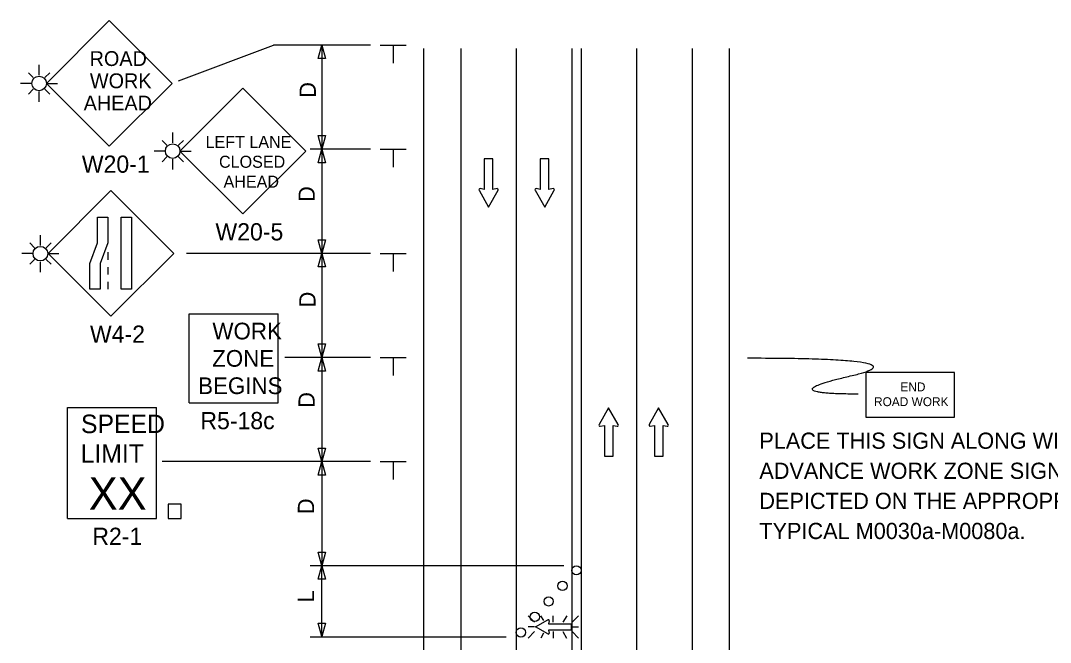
# Model space of a CAD drawing. Extents: x 16731 to 18475, y 7218 to 8213.
# Drawn here: x 16731.1 to 17176, y 7944.5 to 8213.2 of the extents above; entities that cross this region are included whole.
import ezdxf

# ---------------------------------------------------------------- set-up
doc = ezdxf.new("R2010")
doc.units = 0
for name, color, linetype in [('ALI_LEGAL_EX', 7, 'Continuous'), ('MT_SCRATCH_LEVEL_E', 7, 'Continuous'), ('PAVT_EDGE_EX', 7, 'Continuous'), ('TRAFFIC_SIGNS_PR', 7, 'Continuous'), ('TYPICAL_TEXT_DIMEN_PR', 7, 'Continuous')]:
    doc.layers.add(name, color=color, linetype=linetype)

msp = doc.modelspace()

# ---------------------------------------------------------------- linework, layer by layer
at = {"layer": 'ALI_LEGAL_EX'}
for p, q in [((16945.19, 8201.12), (16945.19, 7350.01)), ((16997.19, 8201.12), (16997.19, 7350.01))]:
    msp.add_line(p, q, dxfattribs=at)
for points in [[(16945.19, 8201.12), (16945.19, 8176.12)], [(16997.19, 8201.12), (16997.19, 8176.12)], [(16945.19, 8101.12), (16945.19, 8076.12)], [(16997.19, 8101.12), (16997.19, 8076.12)], [(16945.19, 8001.12), (16945.19, 7976.12)], [(16997.19, 8001.12), (16997.19, 7976.12)]]:
    msp.add_lwpolyline(points, dxfattribs=at)
at = {"layer": 'MT_SCRATCH_LEVEL_E'}
for p, q in [((16935.11, 8153.5), (16931.37, 8153.5)), ((16931.37, 8153.5), (16931.37, 8140.24)), ((16935.11, 8153.5), (16931.37, 8153.5)), ((16931.37, 8153.5), (16931.37, 8140.24)), ((16935.11, 8140.24), (16935.11, 8153.5)), ((16935.11, 8140.24), (16935.11, 8153.5)), ((16959.34, 8153.5), (16955.6, 8153.5)), ((16955.6, 8153.5), (16955.6, 8140.24)), ((16959.34, 8153.5), (16955.6, 8153.5)), ((16955.6, 8153.5), (16955.6, 8140.24)), ((16959.34, 8140.24), (16959.34, 8153.5)), ((16959.34, 8140.24), (16959.34, 8153.5)), ((16929.11, 8139.87), (16933.26, 8132.63)), ((16929.11, 8139.87), (16933.26, 8132.63)), ((16931.37, 8140.24), (16929.59, 8140.56)), ((16931.37, 8140.24), (16929.59, 8140.56)), ((16933.26, 8132.63), (16937.37, 8139.87)), ((16933.26, 8132.63), (16937.37, 8139.87)), ((16936.89, 8140.56), (16935.11, 8140.24)), ((16936.89, 8140.56), (16935.11, 8140.24)), ((16953.35, 8139.87), (16957.49, 8132.63)), ((16953.35, 8139.87), (16957.49, 8132.63)), ((16955.6, 8140.24), (16953.83, 8140.56)), ((16955.6, 8140.24), (16953.83, 8140.56)), ((16957.49, 8132.63), (16961.6, 8139.87)), ((16957.49, 8132.63), (16961.6, 8139.87)), ((16961.12, 8140.56), (16959.34, 8140.24)), ((16961.12, 8140.56), (16959.34, 8140.24)), ((16985.12, 8045.83), (16981.01, 8038.59)), ((16985.12, 8045.83), (16981.01, 8038.59)), ((16989.26, 8038.59), (16985.12, 8045.83)), ((16989.26, 8038.59), (16985.12, 8045.83)), ((17006.72, 8045.83), (17002.61, 8038.59)), ((17006.72, 8045.83), (17002.61, 8038.59)), ((17010.87, 8038.59), (17006.72, 8045.83)), ((17010.87, 8038.59), (17006.72, 8045.83)), ((16981.49, 8037.91), (16983.26, 8038.22)), ((16981.49, 8037.91), (16983.26, 8038.22)), ((16983.26, 8038.22), (16983.26, 8024.97)), ((16983.26, 8038.22), (16983.26, 8024.97)), ((16987.01, 8024.97), (16987.01, 8038.22)), ((16987.01, 8038.22), (16988.78, 8037.91)), ((16987.01, 8024.97), (16987.01, 8038.22)), ((16987.01, 8038.22), (16988.78, 8037.91)), ((17003.09, 8037.91), (17004.87, 8038.22)), ((17003.09, 8037.91), (17004.87, 8038.22)), ((17004.87, 8038.22), (17004.87, 8024.97)), ((17004.87, 8038.22), (17004.87, 8024.97)), ((17008.61, 8024.97), (17008.61, 8038.22)), ((17008.61, 8038.22), (17010.39, 8037.91)), ((17008.61, 8024.97), (17008.61, 8038.22)), ((17008.61, 8038.22), (17010.39, 8037.91)), ((16983.26, 8024.97), (16987.01, 8024.97)), ((16983.26, 8024.97), (16987.01, 8024.97)), ((17004.87, 8024.97), (17008.61, 8024.97)), ((17004.87, 8024.97), (17008.61, 8024.97))]:
    msp.add_line(p, q, dxfattribs=at)
for centre, start, end in [((16929.52, 8140.09), 80.0362, 209.7731), ((16929.52, 8140.09), 80.0362, 209.7731), ((16936.96, 8140.1), 330.4248, 99.9638), ((16936.96, 8140.1), 330.4248, 99.9638), ((16953.76, 8140.09), 80.0362, 209.7731), ((16953.76, 8140.09), 80.0362, 209.7731), ((16961.2, 8140.1), 330.4248, 99.9638), ((16961.2, 8140.1), 330.4248, 99.9638), ((16981.41, 8038.37), 150.4248, 279.9638), ((16981.41, 8038.37), 150.4248, 279.9638), ((16988.85, 8038.37), 260.0362, 29.7731), ((16988.85, 8038.37), 260.0362, 29.7731), ((17003.02, 8038.37), 150.4248, 279.9638), ((17003.02, 8038.37), 150.4248, 279.9638), ((17010.46, 8038.37), 260.0362, 29.7731), ((17010.46, 8038.37), 260.0362, 29.7731)]:
    msp.add_arc(centre, 0.463, start, end, dxfattribs=at)
at = {"layer": 'PAVT_EDGE_EX'}
for p, q in [((16905.19, 8201.12), (16905.19, 7350.01)), ((16921.19, 8201.12), (16921.19, 7350.01)), ((16969.19, 8201.12), (16969.19, 7912.67)), ((16973.19, 8201.12), (16973.19, 7913.05)), ((17021.19, 8201.12), (17021.19, 7350.01)), ((17037.19, 8201.12), (17037.19, 7350.01))]:
    msp.add_line(p, q, dxfattribs=at)
at = {"layer": 'TRAFFIC_SIGNS_PR'}
for p, q in [((16769.35, 8213.18), (16742.19, 8186.03)), ((16796.5, 8186.03), (16769.35, 8213.18)), ((16739.04, 8189.58), (16739.04, 8194.08)), ((16736.53, 8188.54), (16734.43, 8190.65)), ((16741.55, 8188.54), (16743.66, 8190.65)), ((16735.89, 8186.03), (16731.06, 8186.03)), ((16736.53, 8183.52), (16734.43, 8181.42)), ((16739.04, 8178.07), (16739.04, 8182.48)), ((16741.55, 8183.52), (16743.66, 8181.42)), ((16742.19, 8186.03), (16769.35, 8158.88)), ((16742.19, 8186.03), (16747.07, 8186.03)), ((16769.35, 8158.88), (16796.5, 8186.03)), ((16827.08, 8183.94), (16799.92, 8156.79)), ((16854.23, 8156.79), (16827.08, 8183.94)), ((16796.77, 8160.34), (16796.77, 8164.83)), ((16794.26, 8159.3), (16792.16, 8161.4)), ((16799.28, 8159.3), (16801.39, 8161.4)), ((16793.62, 8156.79), (16788.79, 8156.79)), ((16799.92, 8156.79), (16804.8, 8156.79)), ((16799.92, 8156.79), (16827.08, 8129.64)), ((16827.08, 8129.64), (16854.23, 8156.79)), ((16794.26, 8154.28), (16792.16, 8152.17)), ((16796.77, 8148.83), (16796.77, 8153.24)), ((16799.28, 8154.28), (16801.39, 8152.17)), ((16770.07, 8139.73), (16742.92, 8112.58)), ((16797.22, 8112.58), (16770.07, 8139.73)), ((16739.61, 8116.03), (16739.61, 8120.53)), ((16737.1, 8114.99), (16735, 8117.1)), ((16742.12, 8114.99), (16744.23, 8117.1)), ((16736.46, 8112.48), (16731.63, 8112.48)), ((16742.76, 8112.48), (16747.64, 8112.48)), ((16742.92, 8112.58), (16770.07, 8085.42)), ((16768.82, 8113.07), (16768.82, 8109.87)), ((16770.07, 8085.42), (16797.22, 8112.58)), ((16737.1, 8109.97), (16735, 8107.87)), ((16739.61, 8104.52), (16739.61, 8108.93)), ((16742.12, 8109.97), (16744.23, 8107.87)), ((16768.82, 8106.67), (16768.82, 8103.47)), ((16768.82, 8100.27), (16768.82, 8097.07)), ((16803.94, 8048.05), (16803.94, 8086.45)), ((16803.94, 8086.45), (16842.34, 8086.45)), ((16842.34, 8048.05), (16842.34, 8086.45)), ((16751.38, 8046.06), (16789.78, 8046.06)), ((16751.38, 7998.06), (16751.38, 8046.06)), ((16789.78, 7998.06), (16789.78, 8046.06)), ((16803.94, 8048.05), (16842.34, 8048.05)), ((16751.38, 7998.06), (16789.78, 7998.06)), ((16950.31, 7956.02), (16953.13, 7953.2)), ((16955.74, 7956.02), (16956.95, 7953.93)), ((16961.21, 7953.2), (16961.21, 7956.02)), ((16967, 7956.02), (16965.37, 7953.2)), ((16969.3, 7953.2), (16972.12, 7956.02)), ((16953.13, 7951.17), (16950.31, 7951.17)), ((16969.3, 7951.17), (16972.12, 7951.17)), ((16950.31, 7946.32), (16953.13, 7949.14)), ((16957.03, 7948.5), (16955.77, 7946.32)), ((16961.21, 7949.14), (16961.21, 7946.32)), ((16965.35, 7949.14), (16966.97, 7946.32)), ((16969.3, 7949.14), (16972.12, 7946.31))]:
    msp.add_line(p, q, dxfattribs=at)
for points in [[(16768.82, 8128.31), (16768.82, 8117.13), (16765.48, 8108.25), (16765.48, 8097.07), (16760.98, 8097.07), (16760.98, 8108.25), (16764.33, 8117.13), (16764.33, 8128.31)], [(16778.96, 8128.31), (16778.96, 8097.07), (16774.46, 8097.07), (16774.46, 8128.31)], [(17096.17, 8041.85), (17134.57, 8041.85), (17134.57, 8061.05), (17096.17, 8061.05)], [(16794.8, 7998.06), (16800.39, 7998.06), (16800.39, 8004.23), (16794.8, 8004.23)]]:
    msp.add_lwpolyline(points, close=True, dxfattribs=at)
for points in [[(16958.89, 7948.15), (16953.58, 7951.17), (16958.89, 7954.21)], [(16959.39, 7953.85), (16959.16, 7952.55), (16968.88, 7952.55), (16968.88, 7949.81), (16959.16, 7949.81), (16959.39, 7948.51)]]:
    msp.add_lwpolyline(points, dxfattribs=at)
for centre, radius in [((16739.04, 8186.03), 3.15), ((16796.77, 8156.79), 3.15), ((16739.61, 8112.48), 3.15), ((16971.19, 7975.63), 2), ((16965.19, 7968.92), 2), ((16959.19, 7962.21), 2), ((16953.19, 7955.5), 2), ((16947.2, 7948.79), 2)]:
    msp.add_circle(centre, radius, dxfattribs=at)
for centre, start, end in [((16959.05, 7953.91), 350.0407, 118.5167), ((16959.05, 7948.45), 241.1084, 9.2692)]:
    msp.add_arc(centre, 0.341, start, end, dxfattribs=at)
msp.add_open_spline([(17092.98, 8051.79), (17055.19, 8051.79), (17123.21, 8067.27), (17045.07, 8067.27)], degree=2, dxfattribs=at)
at = {"layer": 'TYPICAL_TEXT_DIMEN_PR'}
for p, q in [((16799.32, 8187.1), (16840.31, 8202.61)), ((16882.19, 8202.61), (16840.31, 8202.61)), ((16859.62, 8196.75), (16861.19, 8202.61)), ((16861.19, 8202.61), (16861.19, 8157.61)), ((16861.19, 8202.61), (16862.76, 8196.75)), ((16886.44, 8202.61), (16897.69, 8202.61)), ((16892.07, 8202.61), (16892.07, 8194.83)), ((16861.19, 8196.75), (16859.62, 8196.75)), ((16862.76, 8196.75), (16861.19, 8196.75)), ((16861.19, 8157.61), (16859.62, 8163.48)), ((16859.62, 8163.48), (16861.19, 8163.48)), ((16861.19, 8163.48), (16862.76, 8163.48)), ((16862.76, 8163.48), (16861.19, 8157.61)), ((16882.19, 8157.61), (16856.19, 8157.61)), ((16859.62, 8151.75), (16861.19, 8157.61)), ((16861.19, 8158.26), (16861.19, 8113.26)), ((16861.19, 8157.61), (16862.76, 8151.75)), ((16886.44, 8157.61), (16897.69, 8157.61)), ((16892.07, 8157.61), (16892.07, 8149.83)), ((16861.19, 8151.75), (16859.62, 8151.75)), ((16862.76, 8151.75), (16861.19, 8151.75)), ((16861.19, 8112.61), (16859.62, 8118.48)), ((16859.62, 8118.48), (16861.19, 8118.48)), ((16861.19, 8118.48), (16862.76, 8118.48)), ((16862.76, 8118.48), (16861.19, 8112.61)), ((16882.19, 8112.61), (16802.75, 8112.61)), ((16859.62, 8106.75), (16861.19, 8112.61)), ((16861.19, 8112.61), (16861.19, 8067.61)), ((16861.19, 8112.61), (16862.76, 8106.75)), ((16886.44, 8112.61), (16897.69, 8112.61)), ((16892.07, 8112.61), (16892.07, 8104.83)), ((16861.19, 8106.75), (16859.62, 8106.75)), ((16862.76, 8106.75), (16861.19, 8106.75)), ((16861.19, 8067.61), (16859.62, 8073.48)), ((16859.62, 8073.48), (16861.19, 8073.48)), ((16861.19, 8073.48), (16862.76, 8073.48)), ((16862.76, 8073.48), (16861.19, 8067.61)), ((16882.19, 8067.61), (16845.23, 8067.61)), ((16859.62, 8061.75), (16861.19, 8067.61)), ((16861.19, 8067.61), (16861.19, 8022.61)), ((16861.19, 8067.61), (16862.76, 8061.75)), ((16886.44, 8067.61), (16897.69, 8067.61)), ((16892.07, 8067.61), (16892.07, 8059.83)), ((16861.19, 8061.75), (16859.62, 8061.75)), ((16862.76, 8061.75), (16861.19, 8061.75)), ((16861.19, 8022.61), (16859.62, 8028.48)), ((16859.62, 8028.48), (16861.19, 8028.48)), ((16861.19, 8028.48), (16862.76, 8028.48)), ((16862.76, 8028.48), (16861.19, 8022.61)), ((16882.19, 8022.61), (16792.24, 8022.61)), ((16859.62, 8016.75), (16861.19, 8022.61)), ((16861.19, 8022.61), (16862.76, 8016.75)), ((16861.19, 8022.61), (16861.19, 7977.61)), ((16886.44, 8022.61), (16897.69, 8022.61)), ((16892.07, 8022.61), (16892.07, 8014.83)), ((16861.19, 8016.75), (16859.62, 8016.75)), ((16862.76, 8016.75), (16861.19, 8016.75)), ((16861.19, 7977.61), (16859.62, 7983.48)), ((16859.62, 7983.48), (16861.19, 7983.48)), ((16861.19, 7983.48), (16862.76, 7983.48)), ((16862.76, 7983.48), (16861.19, 7977.61)), ((16965.79, 7977.61), (16856.19, 7977.61)), ((16859.62, 7971.75), (16861.19, 7977.61)), ((16861.19, 7977.61), (16862.76, 7971.75)), ((16861.19, 7946.79), (16861.19, 7977.61)), ((16861.19, 7971.75), (16859.62, 7971.75)), ((16862.76, 7971.75), (16861.19, 7971.75)), ((16861.19, 7947), (16859.62, 7952.86)), ((16859.62, 7952.86), (16861.19, 7952.86)), ((16861.19, 7952.86), (16862.76, 7952.86)), ((16862.76, 7952.86), (16861.19, 7947)), ((16940.78, 7946.79), (16856.19, 7946.79))]:
    msp.add_line(p, q, dxfattribs=at)

# ---------------------------------------------------------------- texts
at = {"layer": 'TRAFFIC_SIGNS_PR'}
for s, height, p in [('ROAD', 6.4, (16760.89, 8193.57)), ('WORK', 6.4, (16761, 8183.97)), ('AHEAD', 6.4, (16758.31, 8174.37)), ('LEFT LANE', 5.2, (16810.96, 8158.18)), ('W20-1', 7.44, (16757.51, 8147.44)), ('CLOSED', 5.2, (16816.79, 8149.58)), ('AHEAD', 5.2, (16818.74, 8140.98)), ('W20-5', 7.44, (16815.25, 8118.2)), ('W4-2', 7.44, (16761.03, 8073.98)), ('WORK', 7.217, (16813.94, 8075.42)), ('ZONE', 7.217, (16813.82, 8063.61)), ('BEGINS', 7.217, (16807.75, 8051.8)), ('END', 3.831, (17111.17, 8052.98)), ('ROAD WORK', 3.831, (17099.78, 8046.59)), ('R5-18c', 7.44, (16808.75, 8036.61)), ('SPEED', 8, (16757.15, 8034.92)), ('PLACE THIS SIGN ALONG WITH THE', 7, (17050.22, 8028.15)), ('LIMIT', 8, (16756.99, 8022.12)), ('ADVANCE WORK ZONE SIGNING AS', 7, (17050.22, 8015.15)), ('XX', 14.031, (16760.49, 8001.82)), ('DEPICTED ON THE APPROPRIATE', 7, (17050.22, 8002.15)), ('TYPICAL M0030a-M0080a.', 7, (17050.22, 7989.15)), ('R2-1', 7.44, (16762.06, 7986.62))]:
    msp.add_text(s, height=height, dxfattribs=at).set_placement(p)
at = {"layer": 'TYPICAL_TEXT_DIMEN_PR'}
for s, p in [('D', (16858.63, 8179.85)), ('D', (16858.15, 8134.83)), ('D', (16858.49, 8089.27)), ('D', (16858.1, 8045.89)), ('D', (16857.83, 7999.94)), ('L', (16857.83, 7961.77))]:
    msp.add_text(s, height=7, rotation=90, dxfattribs=at).set_placement(p)

doc.saveas('drawing.dxf')
